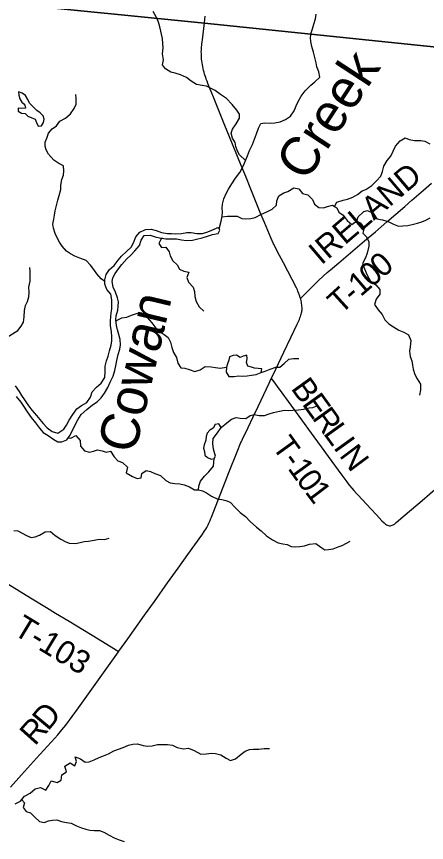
# Model space of a CAD drawing. Extents: x 1442749 to 1756758, y 235267 to 677782.
# Drawn here: x 1584856 to 1590164, y 500562 to 511240 of the extents above; entities that cross this region are included whole.
import ezdxf

# ---------------------------------------------------------------- set-up
doc = ezdxf.new("R2010")
doc.units = 0
for name, color, linetype in [('GM_X_County_Road', 7, 'Continuous'), ('GM_X_County_Road_Text', 7, 'Continuous'), ('GM_X_Major_River', 7, 'Continuous'), ('GM_X_Major_River_Text', 7, 'Continuous'), ('GM_X_Minor_Lake', 7, 'Continuous'), ('GM_X_Minor_River', 7, 'Continuous'), ('GM_X_Township', 7, 'Continuous'), ('GM_X_Township_Road', 7, 'Continuous'), ('GM_X_Township_Road_Text', 7, 'Continuous')]:
    doc.layers.add(name, color=color, linetype=linetype)

msp = doc.modelspace()

# ---------------------------------------------------------------- linework, layer by layer
at = {"layer": 'GM_X_County_Road'}
for points in [[(1588533, 507594), (1588530, 507604), (1588523, 507625), (1588516, 507646), (1588509, 507665), (1588504, 507678), (1588498, 507691), (1588492, 507707), (1588484, 507723), (1588476, 507741), (1588469, 507754), (1588463, 507767), (1588426, 507839), (1588311, 508055), (1588237, 508197), (1588200, 508271), (1588192, 508288), (1588185, 508303), (1588155, 508369), (1588065, 508577), (1588021, 508683), (1587890, 509008), (1587823, 509172), (1587766, 509312), (1587614, 509686), (1587555, 509832), (1587510, 509941), (1587405, 510196), (1587343, 510351), (1587334, 510375), (1587323, 510404), (1587313, 510431), (1587306, 510452), (1587299, 510472), (1587292, 510494), (1587284, 510520), (1587277, 510544), (1587272, 510570), (1587267, 510593), (1587263, 510615), (1587258, 510641), (1587255, 510667), (1587253, 510690), (1587251, 510715), (1587249, 510740), (1587249, 510764), (1587248, 510786), (1587249, 510805), (1587250, 510822), (1587252, 510845), (1587254, 510869), (1587255, 510884), (1587259, 510911), (1587262, 510939), (1587288, 511158), (1587299, 511245)], [(1588154, 506559), (1588178, 506609), (1588316, 506899), (1588408, 507091), (1588489, 507263), (1588518, 507325), (1588526, 507345), (1588532, 507362), (1588538, 507380), (1588542, 507393), (1588545, 507408), (1588548, 507421), (1588550, 507436), (1588552, 507450), (1588552, 507465), (1588552, 507479), (1588551, 507495), (1588550, 507511), (1588547, 507528), (1588544, 507546), (1588540, 507566), (1588536, 507584), (1588533, 507594)], [(1586175, 503026), (1586181, 503035), (1586296, 503195), (1586513, 503499), (1586641, 503678), (1586813, 503918), (1586949, 504107), (1587075, 504283), (1587256, 504537), (1587294, 504594), (1587306, 504614), (1587319, 504636), (1587327, 504651), (1587337, 504667), (1587346, 504688), (1587355, 504706), (1587363, 504726), (1587373, 504750), (1587381, 504769), (1587494, 505055), (1587561, 505233), (1587604, 505346), (1587711, 505611), (1587762, 505731), (1587767, 505744), (1587772, 505756), (1587776, 505765), (1587781, 505776), (1587854, 505928), (1587919, 506064), (1587985, 506199), (1588025, 506282), (1588127, 506502), (1588154, 506559)], [(1584777, 501279), (1584922, 501438), (1585113, 501650), (1585353, 501910), (1585392, 501955), (1585444, 502018), (1585493, 502080), (1585575, 502190), (1585658, 502304), (1586046, 502845), (1586175, 503026)]]:
    msp.add_lwpolyline(points, dxfattribs=at)
at = {"layer": 'GM_X_Major_River'}
for points in [[(1587478, 508495), (1587504, 508595), (1587517, 508657), (1587522, 508709), (1587517, 508763), (1587521, 508815), (1587542, 508885), (1587572, 508950), (1587599, 509006), (1587643, 509079), (1587690, 509151), (1587746, 509222), (1587779, 509281), (1587804, 509335), (1587826, 509389), (1587847, 509440), (1587872, 509508), (1587910, 509586), (1587936, 509653), (1587965, 509723), (1587987, 509795), (1588020, 509858), (1588073, 509867), (1588141, 509860), (1588201, 509867), (1588269, 509877), (1588338, 509910), (1588401, 509953), (1588449, 510020), (1588476, 510086), (1588504, 510143), (1588543, 510211), (1588591, 510280), (1588665, 510353), (1588718, 510396), (1588783, 510456), (1588769, 510525), (1588746, 510590), (1588737, 510640), (1588720, 510711), (1588700, 510779), (1588679, 510852), (1588667, 510917), (1588664, 510967), (1588671, 511029), (1588687, 511083), (1588706, 511141), (1588725, 511212), (1588735, 511272)], [(1587478, 508495), (1587464, 508510), (1587446, 508504)], [(1584841, 506467), (1584890, 506394), (1584921, 506341), (1584969, 506271), (1585002, 506221), (1585055, 506153), (1585114, 506084), (1585159, 506031), (1585202, 505978), (1585252, 505922), (1585320, 505873), (1585393, 505855), (1585469, 505906), (1585502, 505959), (1585537, 506023), (1585585, 506096), (1585637, 506167), (1585698, 506212), (1585767, 506249), (1585812, 506318), (1585836, 506386), (1585891, 506449), (1585951, 506502), (1586000, 506575), (1586002, 506645), (1586006, 506721), (1586023, 506787), (1586042, 506851), (1586060, 506919), (1586082, 506993), (1586091, 507047), (1586090, 507097), (1586085, 507169), (1586075, 507240), (1586072, 507306), (1586076, 507358), (1586081, 507408), (1586090, 507462), (1586091, 507516), (1586090, 507579), (1586076, 507649), (1586027, 507712), (1585999, 507779), (1585998, 507834), (1586015, 507903), (1586061, 507971), (1586122, 508020), (1586172, 508089), (1586217, 508140), (1586281, 508203), (1586342, 508260), (1586369, 508315), (1586401, 508391), (1586454, 508452), (1586527, 508485), (1586598, 508493), (1586665, 508474), (1586735, 508450), (1586809, 508437), (1586863, 508433), (1586917, 508432), (1586991, 508437), (1587063, 508447), (1587116, 508450), (1587192, 508437), (1587264, 508437), (1587332, 508456), (1587383, 508477), (1587446, 508504)], [(1584850, 506326), (1584911, 506253), (1584946, 506202), (1584994, 506128), (1585047, 506055), (1585102, 505986), (1585156, 505918), (1585203, 505863), (1585266, 505822), (1585339, 505770), (1585391, 505743), (1585443, 505740), (1585508, 505766), (1585551, 505828), (1585576, 505885), (1585652, 506028), (1585695, 506094), (1585765, 506160), (1585838, 506219), (1585901, 506258), (1585954, 506309), (1585996, 506372), (1586038, 506446), (1586067, 506515), (1586107, 506591), (1586131, 506665), (1586146, 506744), (1586153, 506794), (1586171, 506870), (1586195, 506938), (1586202, 506996), (1586197, 507065), (1586181, 507131), (1586164, 507188), (1586149, 507246), (1586141, 507319), (1586146, 507369), (1586166, 507445), (1586173, 507497), (1586176, 507551), (1586163, 507605), (1586137, 507678), (1586106, 507741), (1586096, 507813), (1586103, 507863), (1586134, 507919), (1586177, 507978), (1586219, 508036), (1586284, 508106), (1586336, 508156), (1586389, 508213), (1586449, 508280), (1586468, 508347), (1586507, 508409), (1586586, 508413), (1586653, 508392), (1586707, 508381), (1586791, 508367), (1586857, 508365), (1586927, 508366), (1586991, 508355), (1587059, 508345), (1587136, 508349), (1587186, 508362), (1587258, 508377), (1587329, 508402), (1587394, 508420), (1587468, 508437)], [(1587468, 508437), (1587478, 508460), (1587489, 508476), (1587478, 508495)]]:
    msp.add_lwpolyline(points, dxfattribs=at)
at = {"layer": 'GM_X_Minor_Lake'}
for points in [[(1585206, 509871), (1585216, 509913), (1585203, 509955), (1585163, 509994), (1585120, 510027), (1585070, 510071), (1585026, 510122), (1585005, 510168), (1584971, 510217), (1584928, 510251), (1584884, 510268), (1584887, 510224), (1584899, 510175), (1584924, 510135), (1584952, 510110)], [(1584952, 510110), (1584966, 510096), (1584974, 510056), (1584925, 510053), (1584879, 510057), (1584877, 510015), (1584923, 509989), (1584969, 509986), (1585004, 509952), (1585056, 509931), (1585096, 509912), (1585114, 509870), (1585137, 509824), (1585181, 509825), (1585206, 509871)], [(1588023, 506638), (1588030, 506686), (1587984, 506690), (1587938, 506693), (1587898, 506705), (1587852, 506720), (1587833, 506768), (1587841, 506814), (1587836, 506860), (1587791, 506849), (1587751, 506831), (1587705, 506860), (1587659, 506858), (1587615, 506841), (1587604, 506799), (1587586, 506749), (1587575, 506707)], [(1587575, 506707), (1587569, 506643), (1587604, 506588), (1587676, 506588), (1587732, 506595), (1587788, 506592), (1587841, 506596), (1587899, 506605), (1587959, 506614), (1588023, 506638)], [(1587506, 505926), (1587474, 505976), (1587426, 505965), (1587402, 505917), (1587361, 505891), (1587323, 505855), (1587312, 505809), (1587309, 505763), (1587287, 505703), (1587276, 505661), (1587290, 505615), (1587293, 505569), (1587329, 505537), (1587375, 505516), (1587415, 505525)], [(1587415, 505525), (1587433, 505555), (1587408, 505646), (1587399, 505722), (1587402, 505784), (1587457, 505858), (1587506, 505926)]]:
    msp.add_lwpolyline(points, dxfattribs=at)
at = {"layer": 'GM_X_Minor_River'}
for points in [[(1587822, 509379), (1587744, 509451), (1587715, 509501), (1587695, 509558), (1587686, 509610), (1587653, 509667), (1587637, 509733), (1587652, 509785), (1587701, 509853), (1587742, 509928), (1587741, 509978), (1587707, 510031), (1587646, 510102), (1587575, 510179), (1587499, 510234), (1587430, 510285), (1587368, 510314), (1587314, 510338), (1587260, 510349), (1587188, 510360), (1587118, 510405), (1587055, 510450), (1586981, 510485), (1586911, 510507), (1586853, 510520), (1586785, 510563), (1586748, 510614), (1586761, 510682), (1586746, 510758), (1586753, 510834), (1586751, 510892), (1586746, 510955), (1586712, 511107), (1586694, 511166), (1586669, 511228), (1586624, 511307)], [(1585998, 507814), (1585951, 507847), (1585896, 507914), (1585857, 507970), (1585815, 508027), (1585758, 508088), (1585678, 508115), (1585610, 508144), (1585556, 508172), (1585505, 508207), (1585449, 508272), (1585414, 508322), (1585382, 508377), (1585355, 508437), (1585334, 508504), (1585326, 508556), (1585339, 508620), (1585346, 508670), (1585357, 508726), (1585373, 508796), (1585392, 508868), (1585409, 508928), (1585428, 509004), (1585431, 509062), (1585444, 509134), (1585464, 509190), (1585469, 509244), (1585464, 509309), (1585404, 509341), (1585338, 509384), (1585271, 509459), (1585240, 509516), (1585226, 509566), (1585229, 509616), (1585250, 509668), (1585270, 509730), (1585319, 509788), (1585374, 509829), (1585418, 509887), (1585489, 509928), (1585554, 509983), (1585603, 510051), (1585630, 510105), (1585628, 510181), (1585625, 510233)], [(1588972, 508786), (1589002, 508841), (1589084, 508866), (1589142, 508877), (1589211, 508905), (1589269, 508938), (1589330, 508985), (1589380, 509003), (1589457, 509056), (1589518, 509114), (1589571, 509175), (1589594, 509237), (1589611, 509305), (1589655, 509377), (1589700, 509434), (1589733, 509500), (1589764, 509564), (1589823, 509632), (1589886, 509673), (1589941, 509652), (1590007, 509636), (1590090, 509639), (1590142, 509630), (1590207, 509593)], [(1587515, 508649), (1587587, 508658), (1587711, 508657), (1587771, 508630), (1587823, 508626), (1587891, 508627), (1587947, 508642), (1588028, 508683), (1588096, 508713), (1588165, 508750), (1588224, 508802), (1588226, 508856), (1588251, 508920), (1588316, 508959), (1588368, 508980), (1588445, 509026), (1588511, 509013), (1588558, 508950), (1588628, 508937), (1588689, 508874), (1588715, 508816), (1588770, 508771), (1588832, 508766), (1588883, 508784), (1588947, 508803), (1589003, 508765), (1589028, 508712), (1589084, 508673), (1589135, 508605), (1589197, 508552), (1589261, 508597), (1589280, 508649), (1589351, 508720), (1589401, 508734), (1589475, 508699), (1589522, 508626), (1589594, 508613), (1589668, 508592), (1589736, 508554), (1589800, 508531), (1589856, 508532), (1589924, 508537), (1589994, 508557), (1590049, 508570), (1590105, 508587), (1590157, 508607), (1590210, 508638)], [(1589256, 508593), (1589307, 508573), (1589355, 508508), (1589338, 508438), (1589389, 508391), (1589419, 508329), (1589416, 508270), (1589395, 508182), (1589376, 508122), (1589337, 508047), (1589362, 507978), (1589395, 507896), (1589440, 507817), (1589508, 507770), (1589561, 507711), (1589561, 507651), (1589514, 507585), (1589489, 507515), (1589536, 507449), (1589590, 507388), (1589625, 507319), (1589674, 507265), (1589736, 507228), (1589806, 507185), (1589872, 507158), (1589929, 507127), (1589960, 507051), (1589953, 506969), (1589943, 506915), (1589952, 506844), (1589973, 506790), (1589983, 506734), (1589990, 506679), (1590013, 506611), (1590043, 506554), (1590084, 506486), (1590087, 506415), (1590074, 506347)], [(1586747, 508374), (1586723, 508357), (1586698, 508304), (1586734, 508253), (1586788, 508258), (1586831, 508196), (1586845, 508145), (1586880, 508083), (1586938, 508030), (1586965, 507976), (1587023, 507949), (1587089, 507936), (1587062, 507864), (1587081, 507804), (1587143, 507743), (1587162, 507685), (1587165, 507620), (1587181, 507556), (1587222, 507489), (1587281, 507432)], [(1584408, 506864), (1584431, 506922), (1584418, 506974), (1584441, 507040), (1584523, 507053), (1584595, 507050), (1584665, 507063), (1584734, 507093), (1584804, 507138), (1584873, 507181), (1584916, 507235), (1584945, 507287), (1584955, 507357), (1584958, 507439), (1584973, 507503), (1584998, 507557), (1585017, 507617), (1585021, 507671), (1585018, 507741), (1585033, 507819), (1585032, 507875), (1585031, 507946), (1585027, 507996)], [(1586142, 507306), (1586220, 507344), (1586284, 507352), (1586347, 507377), (1586423, 507404), (1586477, 507379), (1586547, 507347), (1586606, 507280), (1586659, 507211), (1586715, 507162), (1586769, 507131), (1586820, 507089), (1586850, 507030), (1586869, 506962), (1586890, 506895), (1586929, 506831), (1586943, 506760), (1586982, 506698), (1587036, 506693), (1587090, 506676), (1587166, 506652), (1587234, 506671), (1587299, 506716), (1587377, 506713), (1587433, 506703), (1587491, 506692), (1587575, 506707), (1587569, 506643), (1587604, 506588), (1587676, 506588), (1587732, 506595), (1587788, 506592), (1587841, 506596), (1587899, 506605), (1587959, 506614), (1588023, 506638), (1588074, 506657), (1588140, 506682), (1588213, 506706), (1588265, 506705), (1588319, 506753), (1588382, 506810), (1588442, 506821), (1588511, 506821)], [(1587214, 505120), (1587218, 505167), (1587237, 505235), (1587290, 505298), (1587347, 505354), (1587406, 505429), (1587415, 505525), (1587433, 505555), (1587408, 505646), (1587399, 505722), (1587402, 505784), (1587457, 505858), (1587506, 505926), (1587581, 505987), (1587639, 506034), (1587698, 506058), (1587750, 506049), (1587824, 506044), (1587880, 506080), (1587933, 506093), (1587997, 506082), (1588067, 506084), (1588125, 506103), (1588182, 506122), (1588262, 506140), (1588324, 506153), (1588378, 506148), (1588433, 506152), (1588505, 506155), (1588571, 506164), (1588643, 506179), (1588693, 506185), (1588756, 506210)], [(1585525, 505792), (1585558, 505791), (1585623, 505825), (1585680, 505758), (1585685, 505684), (1585735, 505627), (1585800, 505608), (1585851, 505622), (1585905, 505639), (1585965, 505624), (1586019, 505608), (1586075, 505621), (1586120, 505548), (1586170, 505494), (1586230, 505473), (1586291, 505412), (1586278, 505342), (1586356, 505295), (1586418, 505268), (1586470, 505278), (1586479, 505330), (1586533, 505371), (1586589, 505358), (1586649, 505330), (1586719, 505307), (1586788, 505240), (1586844, 505211), (1586906, 505202), (1586970, 505200), (1587028, 505187), (1587096, 505158), (1587160, 505123), (1587214, 505121), (1587266, 505108), (1587317, 505081), (1587379, 505037), (1587455, 505006), (1587513, 504995), (1587567, 504984), (1587623, 504960), (1587686, 504891), (1587751, 504828), (1587821, 504775), (1587882, 504712), (1587963, 504637), (1588023, 504590), (1588094, 504527), (1588172, 504476), (1588244, 504435), (1588306, 504424), (1588360, 504414), (1588411, 504389), (1588468, 504382), (1588524, 504388), (1588584, 504399), (1588648, 504418), (1588729, 504427), (1588794, 504380), (1588846, 504346), (1588896, 504349), (1588956, 504357), (1589019, 504382), (1589073, 504403), (1589126, 504431), (1589176, 504458)], [(1584820, 504595), (1584872, 504592), (1584930, 504559), (1584984, 504530), (1585044, 504506), (1585100, 504513), (1585154, 504535), (1585227, 504578), (1585297, 504583), (1585357, 504530), (1585428, 504481), (1585486, 504455), (1585538, 504432), (1585622, 504425), (1585680, 504440), (1585731, 504452), (1585789, 504459), (1585861, 504472), (1585927, 504482), (1585995, 504479), (1586056, 504494)], [(1584841, 501061), (1584908, 501094), (1584961, 501159), (1585033, 501200), (1585096, 501254), (1585165, 501273), (1585238, 501240), (1585275, 501300), (1585306, 501359), (1585382, 501338), (1585433, 501368), (1585444, 501438), (1585504, 501477), (1585483, 501547), (1585550, 501591), (1585610, 501554), (1585634, 501608), (1585617, 501668), (1585683, 501643), (1585747, 501600), (1585799, 501603), (1585861, 501631), (1585928, 501662), (1585984, 501683), (1586047, 501708), (1586116, 501748), (1586178, 501767), (1586239, 501790), (1586307, 501821), (1586363, 501833), (1586422, 501836), (1586494, 501815), (1586548, 501806), (1586612, 501813), (1586680, 501827), (1586744, 501830), (1586811, 501827), (1586877, 501818), (1586936, 501789), (1587020, 501772), (1587081, 501779), (1587155, 501750), (1587242, 501705), (1587312, 501706), (1587379, 501715), (1587433, 501713), (1587503, 501696), (1587570, 501651), (1587628, 501622), (1587691, 501645), (1587764, 501704), (1587818, 501742), (1587873, 501763), (1587923, 501770)], [(1587923, 501770), (1587993, 501767), (1588061, 501775), (1588132, 501776)], [(1584925, 501115), (1584959, 501075), (1584941, 501013), (1584982, 500961), (1585038, 500946), (1585093, 500889), (1585153, 500832), (1585215, 500819), (1585271, 500841), (1585321, 500852), (1585380, 500855), (1585440, 500834), (1585504, 500822), (1585566, 500813), (1585635, 500778), (1585697, 500753), (1585753, 500734), (1585807, 500719), (1585861, 500717), (1585931, 500718), (1585987, 500697), (1586055, 500656), (1586121, 500623), (1586186, 500598), (1586252, 500575)]]:
    msp.add_lwpolyline(points, dxfattribs=at)
at = {"layer": 'GM_X_Township'}
for points in [[(1607409, 509023), (1601349, 509660), (1598207, 509991), (1595438, 510291), (1595355, 510300), (1591670, 510701), (1587291, 511156), (1584741, 511410), (1583705, 511521), (1580873, 511825), (1577466, 512312), (1577336, 518378), (1577247, 522507)], [(1573762, 498986), (1574679, 502300), (1575144, 503972), (1577400, 512074), (1577466, 512312), (1580873, 511825), (1583705, 511521), (1584741, 511410), (1587291, 511156), (1591670, 510701), (1595355, 510300), (1595438, 510291), (1598207, 509991), (1601349, 509660), (1607409, 509023), (1609267, 508822), (1609586, 508788), (1610595, 504741), (1611751, 500101)]]:
    msp.add_lwpolyline(points, dxfattribs=at)
at = {"layer": 'GM_X_Township_Road'}
for points in [[(1588533, 507594), (1588593, 507655), (1588644, 507706), (1588699, 507762), (1588772, 507833), (1588878, 507930), (1588920, 507967), (1589028, 508057), (1589363, 508340), (1589505, 508457), (1589650, 508585), (1589883, 508786), (1589974, 508865), (1590126, 508996), (1590227, 509084)], [(1588154, 506559), (1588187, 506518), (1588231, 506458), (1588291, 506375), (1588454, 506153), (1588512, 506074), (1588705, 505805), (1588799, 505675), (1588890, 505550), (1589066, 505309), (1589131, 505223), (1589149, 505200), (1589168, 505176), (1589198, 505141), (1589223, 505113), (1589257, 505075), (1589279, 505051), (1589442, 504876), (1589517, 504797), (1589586, 504722), (1589614, 504693), (1589634, 504676), (1589645, 504669), (1589659, 504662), (1589671, 504658), (1589684, 504656), (1589697, 504656), (1589708, 504658), (1589720, 504662), (1589732, 504668), (1589749, 504679), (1589773, 504697), (1589887, 504796), (1590106, 504984), (1590306, 505154)], [(1586175, 503026), (1586150, 503042), (1586117, 503064), (1585913, 503190), (1585537, 503418), (1585363, 503523), (1585243, 503596), (1585038, 503721), (1584537, 504026), (1584350, 504143), (1584159, 504259), (1583930, 504399), (1583869, 504437), (1583829, 504462)]]:
    msp.add_lwpolyline(points, dxfattribs=at)

# ---------------------------------------------------------------- texts
at = {"layer": 'GM_X_County_Road_Text'}
for s, rotation, p in [('D', 50.2446, (1585265, 501994)), ('R', 48.2556, (1585094, 501801))]:
    msp.add_text(s, height=300, rotation=rotation, dxfattribs=at).set_placement(p)
at = {"layer": 'GM_X_Major_River_Text'}
for s, rotation, p in [('Creek', 56.8513, (1588604, 509089)), ('Cowan', 76.6868, (1586389, 505574))]:
    msp.add_text(s, height=500, rotation=rotation, dxfattribs=at).set_placement(p)
at = {"layer": 'GM_X_Township_Road_Text'}
for s, rotation, p in [('IRELAND', 40.4157, (1588801, 508019)), ('0', 40.5578, (1589591, 507850)), ('0', 40.5838, (1589450, 507729)), ('1', 40.6758, (1589310, 507609)), ('T', 42.2685, (1589053, 507379)), ('-', 40.951, (1589218, 507528)), ('B', 305.784, (1588400, 506432)), ('E', 305.787, (1588544, 506232)), ('R', 305.784, (1588675, 506050)), ('L', 305.787, (1588819, 505850)), ('T', 305.7873, (1588155, 505681)), ('I', 305.7986, (1588950, 505668)), ('N', 306.7942, (1589026, 505564)), ('-', 305.8029, (1588286, 505499)), ('1', 305.8784, (1588359, 505398)), ('0', 306.152, (1588468, 505247)), ('1', 307.155, (1588580, 505094)), ('T-103', 328.7973, (1584799, 503262))]:
    msp.add_text(s, height=300, rotation=rotation, dxfattribs=at).set_placement(p)

doc.saveas('drawing.dxf')
